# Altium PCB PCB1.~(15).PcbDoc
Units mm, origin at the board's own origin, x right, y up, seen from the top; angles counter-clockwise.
Board outline 49.6 x 17.59 mm, 4 copper layers (Top Layer, Layer 1, Layer 2, Bottom Layer), stack 0.127 mm thick; 1 components, 1 nets, 2 pads, 3 vias.
Unrouted connection lines stored in the file: 19.
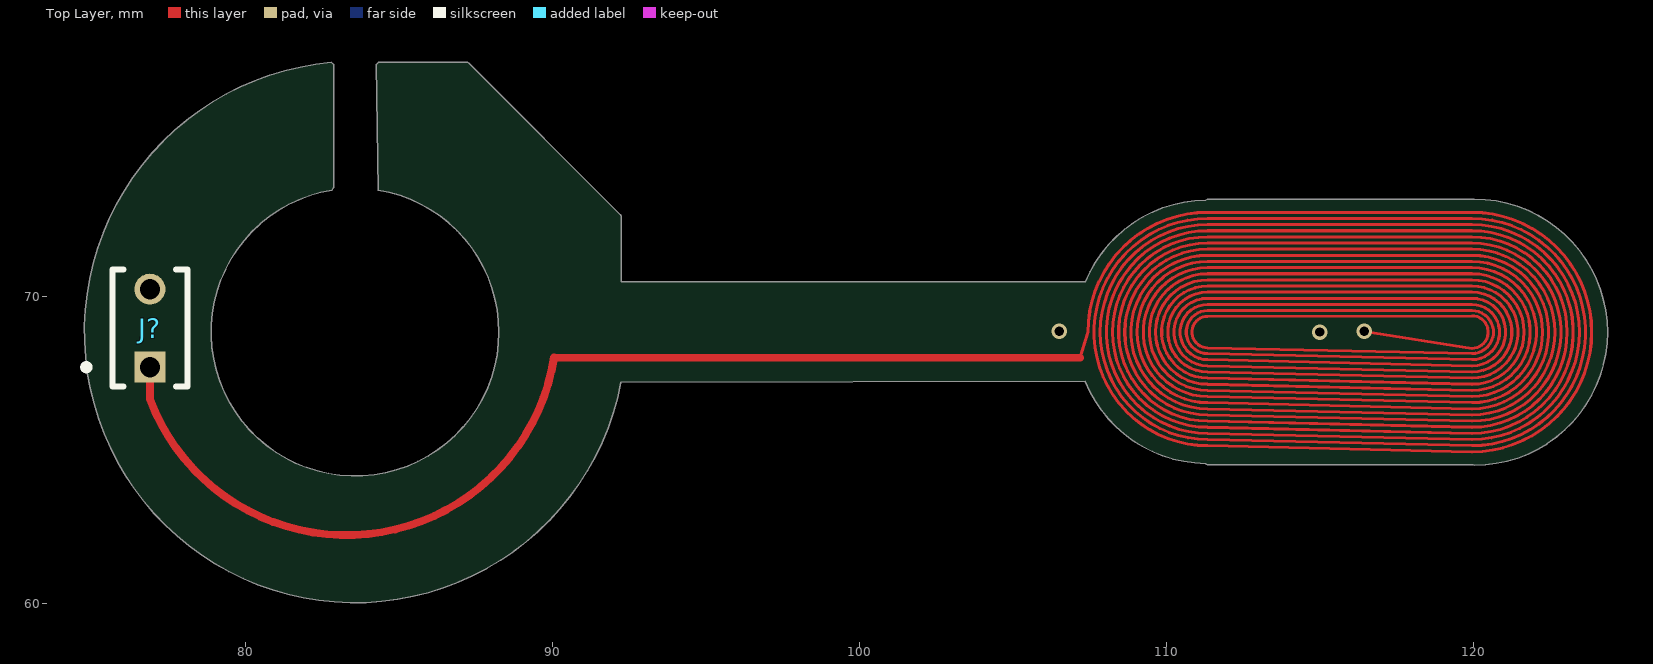
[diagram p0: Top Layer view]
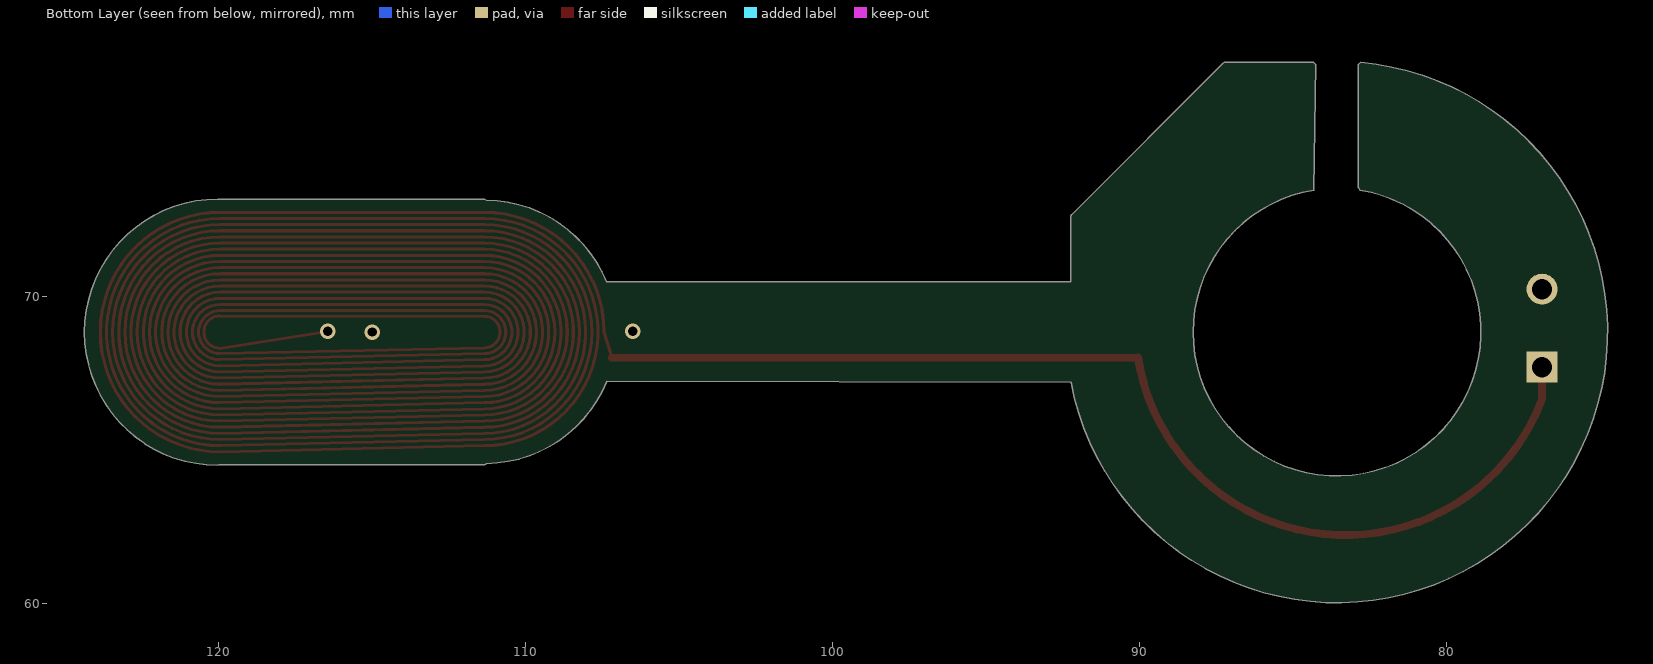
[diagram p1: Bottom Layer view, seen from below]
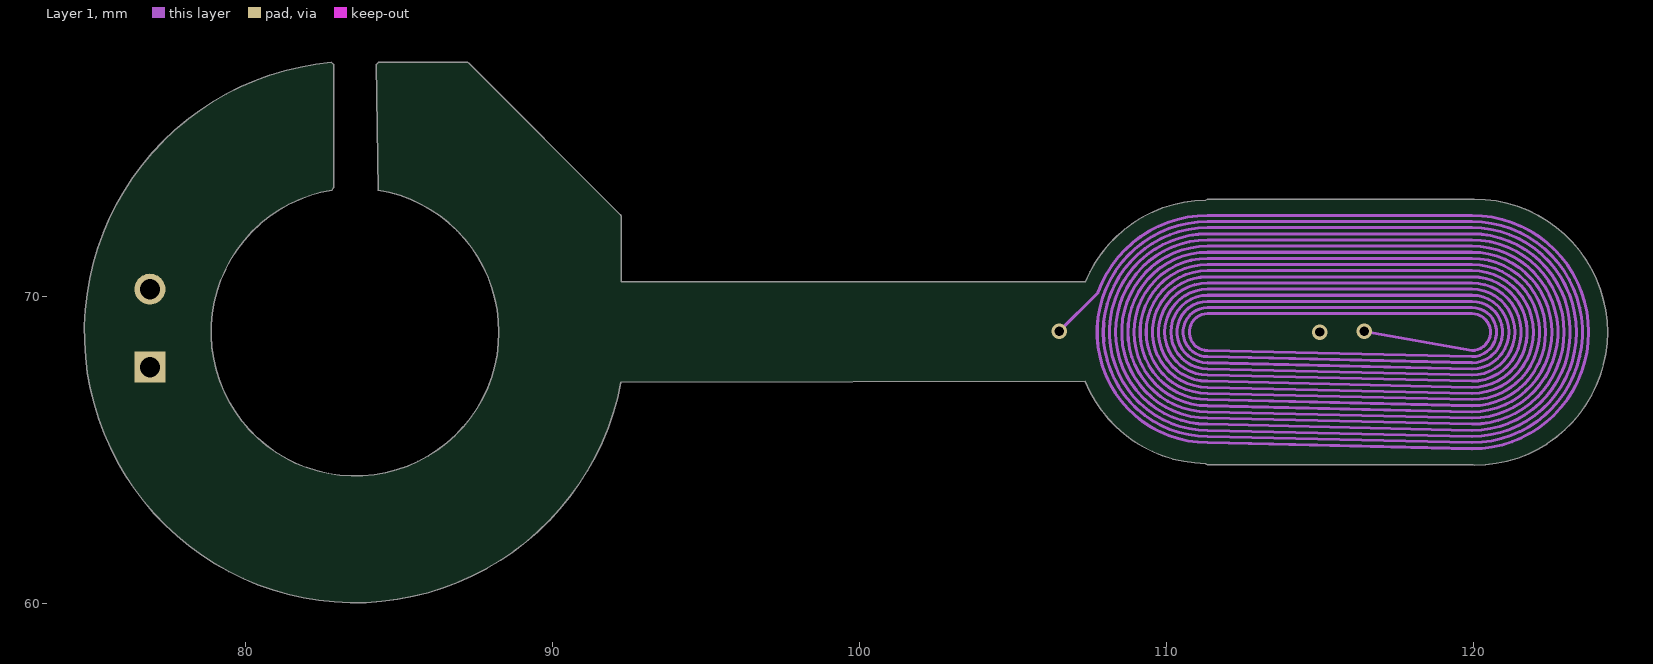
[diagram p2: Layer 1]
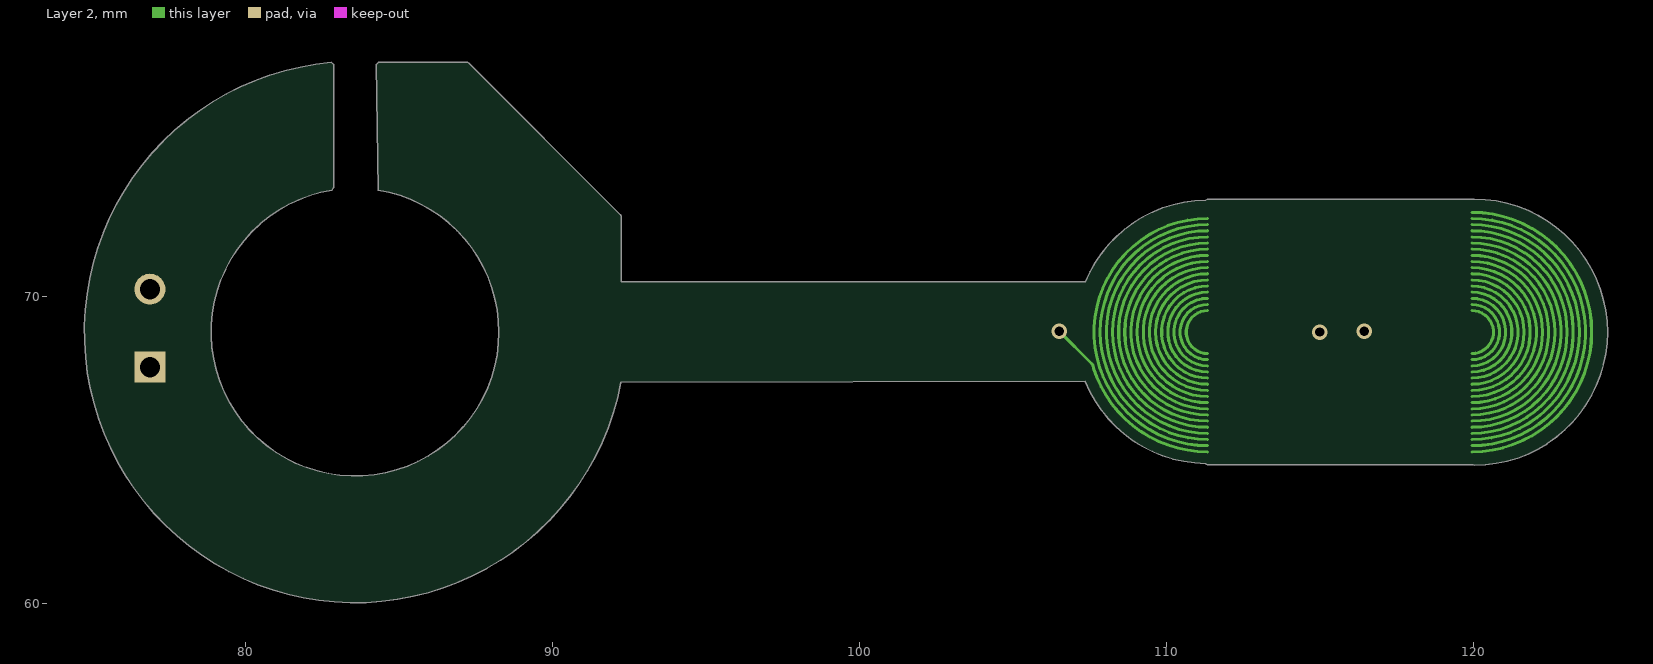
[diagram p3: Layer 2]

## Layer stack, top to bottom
Top Solder: solder mask 0.0102, Solder Resist, Dk 3.5
Top Layer: signal copper 0.0127
Dielectric 2: prepreg 0.0254, PP-006, Dk 3.5
Layer 1: signal copper 0.0127
Dielectric 1: dielectric 0.0254, FR-4, Dk 3.5
Layer 2: signal copper 0.0127
Dielectric 3: prepreg 0.0254, PP-006, Dk 3.5
Bottom Layer: signal copper 0.0127
Bottom Solder: solder mask 0.0102, Solder Resist, Dk 3.5

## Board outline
84.317,73.46 cw(c83.566,68.834) 88.252,68.834 cw(c83.566,68.834) 82.815,73.46 82.867,73.538 82.867,77.551 82.798,77.614 ccw(c83.566,68.834) 92.226,67.195 107.341,67.229 107.345,67.229 ccw(c111.328,68.851) 111.267,64.551 111.328,64.506 119.988,64.506 120.021,64.497 ccw(c120.021,68.831) 124.355,68.831 ccw(c120.021,68.831) 120.017,73.165 111.328,73.165 111.274,73.134 ccw(c111.328,68.834) 107.35,70.468 107.326,70.473 92.245,70.473 92.234,70.483 92.234,72.604 92.216,72.649 87.269,77.596 87.224,77.615 84.329,77.615 84.265,77.551

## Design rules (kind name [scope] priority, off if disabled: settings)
Clearance [All] p1: gap=0.254 ignorepadtopadclearanceinfootprint=FALSE except(0: Arc-Hole Track-Hole SMDPad-Hole THPad-Hole Via-Hole Fill-Hole Poly-Hole Region-Hole Text-Hole; 0.1: Arc-Arc Arc-Track Arc-Via Track-Track Track-Via)
PolygonConnect [All] p1: connectstyle=Relief reliefconductorwidth=0.254 reliefentries=4 polygonreliefangle="90 Angle" airgapwidth=0.254
RoutingVias [All] p1: holewidth=0.711 width=1.27 viastyle="Through Hole" minholewidth=0.711 minwidth=1.27 maxholewidth=0.711 maxwidth=1.27
SolderMaskExpansion [All] p1: expansion=0.102 istentingtop=FALSE
Width [All] p1: maxlimit=0.254 minlimit=0.1 preferedwidth=0.1 minimp=50.000000 maximp=50.000000 favimp=50.000000
30 further rules are at their usual default settings.

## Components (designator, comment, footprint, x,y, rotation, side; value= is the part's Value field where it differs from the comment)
J? "TMS-103-59-L-S-002" SAMTEC_TMS-103-59-L-S-002 76.886,68.961 r90 top

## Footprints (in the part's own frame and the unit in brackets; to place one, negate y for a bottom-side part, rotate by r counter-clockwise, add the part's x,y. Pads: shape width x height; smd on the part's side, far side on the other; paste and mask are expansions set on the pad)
SAMTEC_TMS-103-59-L-S-002 [mm]
  rect 1.01x1.01 hole 0.66: 01(-1.27,0)
  round 1.01 hole 0.66: 03(1.27,0)
  silkscreen extent -1.91,-1.22 1.91,2.17

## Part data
J?: Package=None

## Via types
v1: diameter 0.5/0.5/0.5/0.5 (per signal layer), hole 0.3, Top Layer to Bottom Layer, 3 vias

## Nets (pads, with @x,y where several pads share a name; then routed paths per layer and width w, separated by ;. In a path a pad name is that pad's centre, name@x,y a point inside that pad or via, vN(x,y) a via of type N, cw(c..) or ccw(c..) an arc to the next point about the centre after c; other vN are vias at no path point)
NetJ?_01: J?.01 J?.03 | length 1231.1
  Top Layer w0.1: 107.175,67.996 107.433,68.834 cw(c111.333,68.834) 111.333,72.734 119.939,72.734 cw(c119.939,68.834) 119.939,64.934 111.333,65.134 cw(c111.333,68.834) 111.333,72.534 119.939,72.534 cw(c119.939,68.834) 119.939,65.134 111.333,65.334 cw(c111.333,68.834) 111.333,72.334 119.939,72.334 cw(c119.939,68.834) 119.939,65.334 111.333,65.534 cw(c111.333,68.834) 111.333,72.134 119.939,72.134 cw(c119.939,68.834) 119.939,65.534 111.333,65.734 cw(c111.333,68.834) 111.333,71.934 119.939,71.934 cw(c119.939,68.834) 119.939,65.734 111.333,65.934 cw(c111.333,68.834) 111.333,71.734 119.939,71.734 cw(c119.939,68.834) 119.939,65.934 111.333,66.134 cw(c111.333,68.834) 111.333,71.534 119.939,71.534 cw(c119.939,68.834) 119.939,66.134 111.333,66.334 cw(c111.333,68.834) 111.333,71.334 119.939,71.334 cw(c119.939,68.834) 119.939,66.334 111.333,66.534 cw(c111.333,68.834) 111.333,71.134 119.939,71.134 cw(c119.939,68.834) 119.939,66.534 111.333,66.734 cw(c111.333,68.834) 111.333,70.934 119.939,70.934 cw(c119.939,68.834) 119.939,66.734 111.333,66.934 cw(c111.333,68.834) 111.333,70.734 119.939,70.734 cw(c119.939,68.834) 119.939,66.934 111.333,67.134 cw(c111.333,68.834) 111.333,70.534 119.939,70.534 cw(c119.939,68.834) 119.939,67.134 111.333,67.334 cw(c111.333,68.834) 111.333,70.334 119.939,70.334 cw(c119.939,68.834) 119.939,67.334 111.333,67.534 cw(c111.333,68.834) 111.333,70.134 119.939,70.134 cw(c119.939,68.834) 119.939,67.534 111.333,67.734 cw(c111.333,68.834) 111.333,69.934 119.939,69.934 cw(c119.939,68.834) 119.939,67.734 111.333,67.934 cw(c111.333,68.834) 111.333,69.734 119.939,69.734 cw(c119.939,68.834) 119.939,67.934 111.333,68.134 cw(c111.333,68.834) 111.333,69.534 119.939,69.534 ; v1(116.434,68.859) 119.939,68.304 ccw(c119.939,68.834) 119.939,69.364 111.333,69.347 ccw(c111.333,68.834) 111.333,68.321 119.939,68.134 ccw(c119.939,68.834) 119.939,69.534 ; 119.939,69.537 119.939,69.534
  Top Layer w0.254: J?.01 76.886,66.648 ccw(c83.287,69.063) 90.046,68.007 ; 90.116,67.996 107.175,67.996
  Layer 1 w0.1: v1(106.502,68.859) 107.752,70.109 ccw(c107.728,70.134) 107.762,70.134 cw(c111.333,68.834) 111.333,72.634 119.939,72.634 cw(c119.939,68.834) 119.939,65.034 111.333,65.234 cw(c111.333,68.834) 111.333,72.434 119.939,72.434 cw(c119.939,68.834) 119.939,65.234 111.333,65.434 cw(c111.333,68.834) 111.333,72.234 119.939,72.234 cw(c119.939,68.834) 119.939,65.434 111.333,65.634 cw(c111.333,68.834) 111.333,72.034 119.939,72.034 cw(c119.939,68.834) 119.939,65.634 111.333,65.834 cw(c111.333,68.834) 111.333,71.834 119.939,71.834 cw(c119.939,68.834) 119.939,65.834 111.333,66.034 cw(c111.333,68.834) 111.333,71.634 119.939,71.634 cw(c119.939,68.834) 119.939,66.034 111.333,66.234 cw(c111.333,68.834) 111.333,71.434 119.939,71.434 cw(c119.939,68.834) 119.939,66.234 111.333,66.434 cw(c111.333,68.834) 111.333,71.234 119.939,71.234 cw(c119.939,68.834) 119.939,66.434 111.333,66.634 cw(c111.333,68.834) 111.333,71.034 119.939,71.034 cw(c119.939,68.834) 119.939,66.634 111.333,66.834 cw(c111.333,68.834) 111.333,70.834 119.939,70.834 cw(c119.939,68.834) 119.939,66.834 111.333,67.034 cw(c111.333,68.834) 111.333,70.634 119.939,70.634 cw(c119.939,68.834) 119.939,67.034 111.333,67.234 cw(c111.333,68.834) 111.333,70.434 119.939,70.434 cw(c119.939,68.834) 119.939,67.234 111.333,67.434 cw(c111.333,68.834) 111.333,70.234 119.939,70.234 cw(c119.939,68.834) 119.939,67.434 111.333,67.634 cw(c111.333,68.834) 111.333,70.034 119.939,70.034 cw(c119.939,68.834) 119.939,67.634 111.333,67.834 cw(c111.333,68.834) 111.333,69.834 119.939,69.834 cw(c119.939,68.834) 119.939,67.834 111.333,68.034 cw(c111.333,68.834) 111.333,69.634 119.939,69.634 cw(c119.939,68.834) 119.939,68.034 111.333,68.234 cw(c111.333,68.834) 111.333,69.434 119.939,69.434 cw(c119.939,68.834) 119.939,68.234 v1(116.434,68.859)
  Layer 2 w0.1: v1(106.502,68.859) 107.551,67.81 cw(c107.399,67.658) 107.615,67.658 ccw(c111.333,68.834) 111.333,64.934 ; 111.333,65.134 cw(c111.333,68.834) 111.333,72.534 ; 111.333,65.334 cw(c111.333,68.834) 111.333,72.334 ; 111.333,65.534 cw(c111.333,68.834) 111.333,72.134 ; 111.333,65.734 cw(c111.333,68.834) 111.333,71.934 ; 111.333,65.934 cw(c111.333,68.834) 111.333,71.734 ; 111.333,66.134 cw(c111.333,68.834) 111.333,71.534 ; 111.333,66.334 cw(c111.333,68.834) 111.333,71.334 ; 111.333,66.534 cw(c111.333,68.834) 111.333,71.134 ; 111.333,66.734 cw(c111.333,68.834) 111.333,70.934 ; 111.333,66.934 cw(c111.333,68.834) 111.333,70.734 ; 111.333,67.134 cw(c111.333,68.834) 111.333,70.534 ; 111.333,67.334 cw(c111.333,68.834) 111.333,70.334 ; 111.333,67.534 cw(c111.333,68.834) 111.333,70.134 ; 111.333,67.734 cw(c111.333,68.834) 111.333,69.934 ; 111.333,67.934 cw(c111.333,68.834) 111.333,69.734 ; 111.333,68.134 cw(c111.333,68.834) 111.333,69.534 ; 119.939,64.934 ccw(c119.939,68.834) 119.939,72.734
  other v1: 114.986,68.834
copper on no net: | length 110.6
  Layer 2 w0.1: 119.939,65.134 ccw(c119.939,68.834) 119.939,72.534 ; 119.939,65.334 ccw(c119.939,68.834) 119.939,72.334 ; 119.939,65.534 ccw(c119.939,68.834) 119.939,72.134 ; 119.939,65.734 ccw(c119.939,68.834) 119.939,71.934 ; 119.939,65.934 ccw(c119.939,68.834) 119.939,71.734 ; 119.939,66.134 ccw(c119.939,68.834) 119.939,71.534 ; 119.939,66.334 ccw(c119.939,68.834) 119.939,71.334 ; 119.939,66.534 ccw(c119.939,68.834) 119.939,71.134 ; 119.939,66.734 ccw(c119.939,68.834) 119.939,70.934 ; 119.939,66.934 ccw(c119.939,68.834) 119.939,70.734 ; 119.939,67.134 ccw(c119.939,68.834) 119.939,70.534 ; 119.939,67.334 ccw(c119.939,68.834) 119.939,70.334 ; 119.939,67.534 ccw(c119.939,68.834) 119.939,70.134 ; 119.939,67.734 ccw(c119.939,68.834) 119.939,69.934 ; 119.939,67.934 ccw(c119.939,68.834) 119.939,69.734 ; 119.939,68.134 ccw(c119.939,68.834) 119.939,69.534

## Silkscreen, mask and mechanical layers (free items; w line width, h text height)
Mechanical 1:
  lines w0.1: 107.373,70.39 cw(c111.328,68.834) 111.328,73.084 ; 107.374,67.293 ccw(c111.328,68.851) 111.328,64.601
  lines w0.127: 82.803,73.534 82.803,77.551 ccw(c83.566,68.834) 92.171,67.245 ; 82.805,73.523 ccw(c83.566,68.834) 84.327,73.523 ; 84.329,73.534 84.329,77.551 87.224,77.551 89.753,75.021 92.171,72.604 92.171,70.483 92.245,70.409 107.326,70.409 ; 92.183,67.259 107.341,67.292 ; 111.328,64.57 120.021,64.57 ; 111.328,73.101 120.018,73.101 cw(c120.021,68.831) 120.021,64.561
